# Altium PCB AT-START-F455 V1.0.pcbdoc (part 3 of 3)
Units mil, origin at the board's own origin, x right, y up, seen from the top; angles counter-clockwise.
Board outline 10945.53 x 3554 mil, 2 copper layers (Top Layer, Bottom Layer); 149 components, 197 nets, 740 pads, 768 vias.
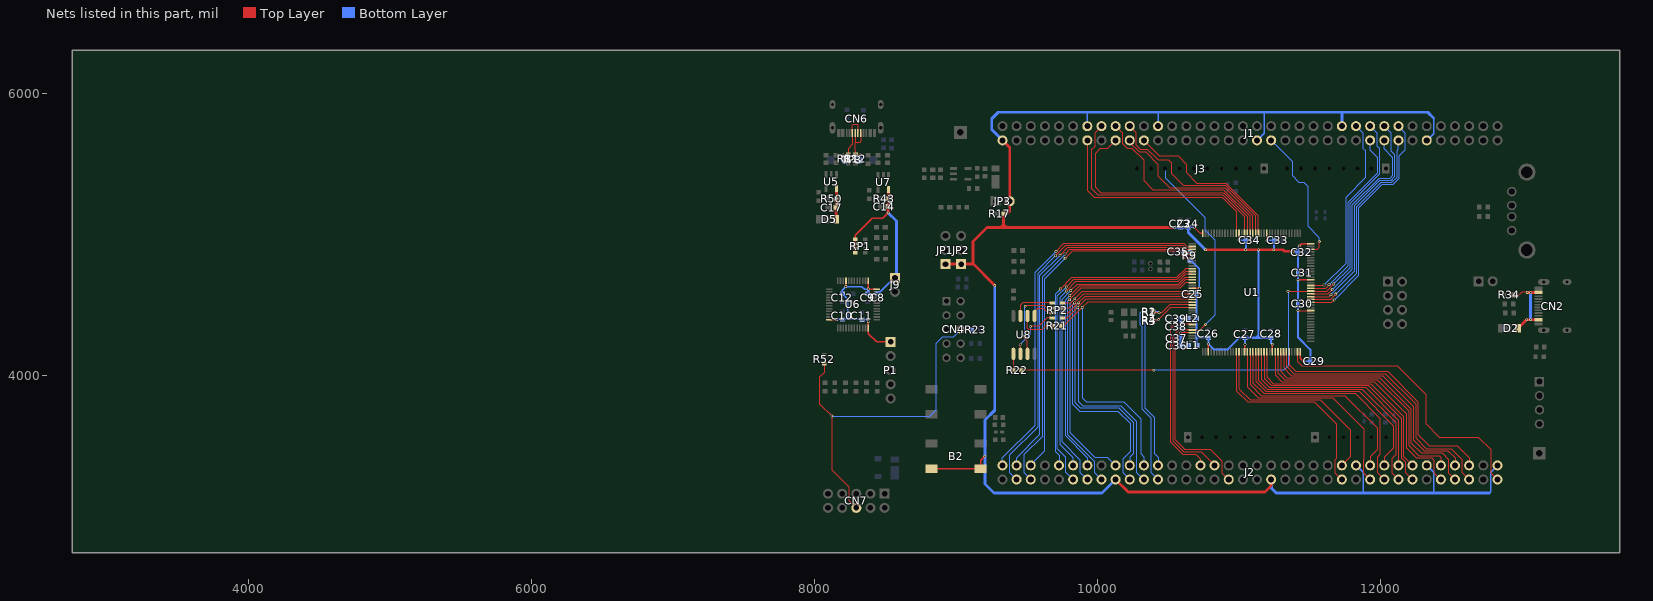
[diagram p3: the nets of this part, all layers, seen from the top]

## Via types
v1: diameter 19.7, hole 11.8, Top Layer to Bottom Layer, 425 vias
v2: diameter 19.68, hole 11.81, Top Layer to Bottom Layer, 331 vias
v3: diameter 31.5, hole 19.68, Top Layer to Bottom Layer, 10 vias
v4: diameter 27.56, hole 19.68, Top Layer to Bottom Layer, 2 vias

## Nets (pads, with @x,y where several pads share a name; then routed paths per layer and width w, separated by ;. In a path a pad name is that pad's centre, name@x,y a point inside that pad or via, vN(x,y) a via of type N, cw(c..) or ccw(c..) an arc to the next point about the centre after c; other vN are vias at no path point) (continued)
PE3: J2.2 U1.2 | length 2667
  Top Layer w6: v2(9708.16,4881.98) 9762.56,4936.38 10610.76,4936.38 10632.36,4914.78 U1.2@10671.86,4914.79
  Bottom Layer w6: J2.2@9329.16,3367.18 9329.16,3419.48 9560.26,3650.58 9560.26,4734.08 v2(9708.16,4881.98)
PE4: J2.3 U1.3 | length 2747.9
  Top Layer w6: v2(9703.83,4849.3) 9777.11,4922.58 10603.26,4922.58 10630.76,4895.08 U1.3@10671.86,4895.11
  Bottom Layer w6: J2.3@9429.17,3267.08 9378.26,3318.08 9378.26,3437.48 9578.26,3637.48 9578.26,4723.73 v2(9703.83,4849.3)
PE5: J2.4 U1.4 | length 2586.6
  Top Layer w6: v2(9736.21,4853.97) 9791.36,4909.18 10595.36,4909.18 10629.16,4875.38 U1.4@10671.86,4875.42
  Bottom Layer w6: J2.4@9429.17,3367.08 9429.16,3421.38 9594.26,3586.48 9594.26,4711.98 v2(9736.21,4853.97)
PE6: J2.5 U1.5 | length 2664.6
  Top Layer w6: v2(9771.79,4861.65) 9805.52,4895.38 10585.96,4895.38 10625.66,4855.68 U1.5@10671.86,4855.74
  Bottom Layer w6: J2.5@9529.16,3267.18 9481.96,3314.38 9481.96,3444.28 9612.26,3574.58 9612.26,4702.12 v2(9771.79,4861.65)
PE7: J2.58 U1.58 | length 1605.7
  Top Layer w6: U1.58@11159.16,4171.68 11159.16,3975.88 11216.06,3918.98 11897.66,3918.98 12129.16,3687.48 J2.58@12129.17,3367.08
PE8: J2.59 U1.59 | length 1740.3
  Top Layer w6: U1.59@11178.76,4171.68 11178.76,3984.18 11229.96,3932.98 11913.96,3932.98 12147.96,3698.98 12147.96,3422.08 12178.26,3391.68 12178.26,3318.08 J2.59@12229.17,3267.08
PE9: J2.60 U1.60 | length 1635.5
  Top Layer w6: U1.60@11198.46,4171.68 11198.46,3992.68 11245.36,3945.78 11935.06,3945.78 12164.76,3716.08 12164.76,3431.48 J2.60@12229.17,3367.08
PE10: J2.63 U1.63 | length 1835.9
  Top Layer w6: U1.63@11257.56,4171.68 11257.56,4006.68 11304.26,3959.98 11956.66,3959.98 12183.66,3733.08 12183.66,3490.58 12254.26,3419.98 12363.16,3419.98 12380.26,3402.88 12380.26,3316.08 J2.63@12429.17,3267.08
PE11: J2.64 U1.64 | length 1749.5
  Top Layer w6: U1.64@11277.26,4171.68 11277.26,4020.88 11323.96,3974.18 11978.36,3974.18 12200.56,3751.98 12200.56,3508.18 12272.76,3435.98 12416.86,3435.98 12429.16,3423.68 J2.64@12429.17,3367.08
PE12: J2.65 U1.65 | length 1887.8
  Top Layer w6: U1.65@11296.86,4171.68 11296.86,4031.28 11339.76,3988.38 11998.46,3988.38 12217.86,3768.98 12217.86,3525.98 12288.86,3454.98 12437.26,3454.98 12480.26,3411.98 12480.26,3316.08 J2.65@12529.17,3267.08
PE13: J2.66 U1.66 | length 1784.8
  Top Layer w6: U1.66@11316.56,4171.68 11316.56,4056.58 11370.56,4002.58 12017.36,4002.58 12233.26,3786.68 12233.26,3546.78 12310.06,3469.98 12479.06,3469.98 12529.16,3419.88 J2.66@12529.17,3367.08
PE14: J2.67 U1.67 | length 1920.6
  Top Layer w6: U1.67@11336.26,4171.68 11336.26,4069.88 11389.36,4016.78 12035.46,4016.78 12250.66,3801.58 12250.66,3562.78 12327.46,3485.98 12501.66,3485.98 12578.26,3409.38 12578.26,3318.08 J2.67@12629.17,3267.08
PE15: J2.68 U1.68 | length 1827.5
  Top Layer w6: U1.68@11355.96,4171.68 11355.96,4079.18 11404.26,4030.98 12053.96,4030.98 12266.36,3818.58 12266.36,3588.48 12347.96,3506.88 12544.16,3506.88 12629.16,3421.88 J2.68@12629.17,3367.08
PF0: J2.10 U1.10 | length 2266
  Top Layer w6: v2@9738.26,4613.98 9817.16,4692.88 10559.16,4692.88 10623.56,4757.28 U1.10@10671.86,4757.31
  Bottom Layer w6: J2.10@9729.26,3367.08 9729.26,3438.98 9702.26,3465.88 9702.26,4577.98 v2@9738.26,4613.98
  other v2: 9738.21,4613.97
PF1: J2.11 U1.11 | length 2370.2
  Top Layer w6: v2(9780.26,4627.98) 9830.56,4678.28 10562.56,4678.28 10621.86,4737.58 U1.11@10671.86,4737.63
  Bottom Layer w6: v2(9780.26,4627.98) 9717.36,4565.08 9717.36,3484.78 9778.26,3423.88 9778.26,3318.08 J2.11@9829.16,3267.18
PF2: J2.12 U1.12 | length 2230
  Top Layer w6: v2(9780.26,4599.98) 9844.36,4664.08 10568.36,4664.08 10622.16,4717.88 U1.12@10671.86,4717.94
  Bottom Layer w6: v2(9780.26,4599.98) 9736.26,4555.98 9736.26,3513.48 9829.16,3420.48 J2.12@9829.17,3367.08
PF3: J2.13 U1.13 | length 2334.4
  Top Layer w6: v2(9812.26,4603.98) 9856.96,4648.68 10571.76,4648.68 10621.36,4698.28 U1.13@10671.86,4698.26
  Bottom Layer w6: v2(9812.26,4603.98) 9751.26,4542.98 9751.26,3533.58 9880.26,3404.48 9880.26,3316.18 J2.13@9929.16,3267.18
PF4: J2.14 U1.14 | length 2192.5
  Top Layer w6: v2@9804.26,4567.98 9870.46,4634.18 10576.36,4634.18 10620.76,4678.58 U1.14@10671.86,4678.57
  Bottom Layer w6: v2@9804.26,4567.98 9772.26,4535.98 9772.26,3578.68 9929.16,3421.78 J2.14@9929.16,3367.18
  other v2: 9804.21,4567.97
PF5: J2.15 U1.15 | length 2295.9
  Top Layer w6: v2(9802.21,4537.97) 9884.16,4619.98 10582.26,4619.98 10621.16,4658.88 U1.15@10671.86,4658.89
  Bottom Layer w6: v2(9802.21,4537.97) 9788.26,4523.18 9788.26,3587.98 9978.26,3397.88 9978.26,3318.08 J2.15@10029.17,3267.08
PF6: J2.18 RP2.4 U1.18 | length 2334.4
  Top Layer w6: RP2.4@9753.18,4516.15 9810.38,4516.15 v2(9840.21,4545.97) 9894.02,4599.78 U1.18@10671.86,4599.83
  Bottom Layer w6: v2(9840.21,4545.97) 9804.26,4509.98 9804.26,3601.88 9980.26,3425.88 10070.36,3425.88 J2.18@10129.16,3367.18
PF7: J2.19 RP2.3 U1.19 | length 2587.3
  Top Layer w6: RP2.3@9753.77,4480.48 cw(c9753.77,4481.3) RP2.3@9753.18,4480.72 9802.95,4480.72 v2(9838.21,4515.97) cw(c9838.28,4515.97) v2(9838.21,4515.97) 9861,4538.79 9902.37,4580.16 U1.19@10671.86,4580.18 ; 9960.77,4580.16 cw(c9960.77,4580.09) 9960.82,4580.14
  Bottom Layer w6: v2@9838.26,4515.98 9822.26,4499.98 9822.26,3803.88 9874.56,3751.58 10145.06,3751.58 10231.76,3664.88 10231.76,3464.78 10178.26,3411.28 10178.26,3318.08 J2.19@10229.16,3267.18
PF8: J2.20 RP2.2 U1.20 | length 2467.4
  Top Layer w6: RP2.2@9754.46,4445.81 ccw(c9754.46,4444.01) RP2.2@9753.18,4445.28 9795.51,4445.28 v2(9866.21,4515.97) 9910.7,4560.46 U1.20@10671.86,4560.46
  Bottom Layer w6: v2(9866.21,4515.97) 9840.26,4489.98 9840.26,3813.88 9880.26,3773.98 10150.66,3773.98 10253.86,3670.78 10253.86,3449.38 10229.16,3424.68 J2.20@10229.17,3367.08
PF9: J2.21 RP2.1 U1.21 | length 2542.3
  Top Layer w6: RP2.1@9753.89,4409.56 cw(c9753.89,4410.55) RP2.1@9753.18,4409.85 9788.08,4409.85 v2(9862.21,4483.97) 9919.02,4540.78 U1.21@10671.86,4540.78
  Bottom Layer w6: v2(9862.21,4483.97) 9864.26,4481.88 9864.26,3820.78 9896.06,3788.98 10166.36,3788.98 10276.26,3679.08 10276.26,3320.08 J2.21@10329.17,3267.08
PF10: J2.22 R21.1 U1.22 | length 2450
  Top Layer w6: R21.1@9744.84,4353.85 9763.43,4353.85 v2(9893.22,4483.63) 9930.67,4521.08 U1.22@10671.86,4521.09 ; v2@9899.22,4483.63 cw(c9900.17,4483.63) v2@9899.5,4484.31
  Bottom Layer w6: v2(9893.22,4483.63) 9893.22,3843.86 9920.1,3816.98 10186.05,3816.98 10307.4,3695.63 10307.4,3451.35 10329.18,3429.57 J2.22@10329.17,3367.08
PF11: J2.49 U1.49 | length 1497.2
  Top Layer w6: U1.49@10981.96,4171.68 10981.96,3896.18 11062.36,3815.78 11534.46,3815.78 11688.26,3661.98 11688.26,3413.98 11680.26,3405.98 11680.26,3316.08 J2.49@11729.17,3267.08
PF12: J2.50 U1.50 | length 1445.9
  Top Layer w6: U1.50@11001.66,4171.68 11001.66,3910.68 11081.96,3830.38 11577.96,3830.38 11788.86,3619.48 11788.86,3426.78 J2.50@11729.17,3367.08
PF13: J2.53 U1.53 | length 1575.8
  Top Layer w6: U1.53@11060.66,4171.68 11060.66,3924.48 11138.96,3846.18 11664.56,3846.18 11884.56,3626.18 11884.56,3409.98 11880.26,3405.68 11880.26,3316.08 J2.53@11929.17,3267.08
PF14: J2.54 U1.54 | length 1544.8
  Top Layer w6: U1.54@11080.36,4171.68 11080.36,3940.78 11160.06,3861.08 11751.16,3861.08 11980.26,3631.98 11980.26,3478.88 11929.16,3427.78 J2.54@11929.17,3367.08
PF15: J2.55 U1.55 | length 1683.1
  Top Layer w6: U1.55@11100.06,4171.68 11100.06,3951.08 11175.46,3875.68 11822.06,3875.68 11996.26,3701.48 11996.26,3442.88 11978.26,3424.88 11978.26,3318.08 J2.55@12029.17,3267.08
PG0: J2.56 U1.56 | length 1620.4
  Top Layer w6: U1.56@11119.76,4171.68 11119.76,3960.88 11190.36,3890.28 11850.66,3890.28 12092.26,3648.68 12092.26,3488.38 12029.16,3425.28 J2.56@12029.17,3367.08
PG1: J2.57 U1.57 | length 1733
  Top Layer w6: U1.57@11139.46,4171.68 11139.46,3967.48 11202.06,3904.98 11874.96,3904.98 12109.56,3670.38 12109.56,3443.88 12080.26,3414.58 12080.26,3316.08 J2.57@12129.17,3267.08
PG2: J1.15 U1.87 | length 1675.9
  Top Layer w6: U1.87@11508.56,4521.08 11659.26,4521.08 v2@11674.26,4535.98
  Bottom Layer w6: v2@11674.26,4535.98 11848.26,4709.98 11848.26,5187.98 12014.26,5353.98 12091.46,5353.98 12136.26,5398.78 12136.26,5557.98 12178.26,5599.98 12178.26,5716.58 J1.15@12129.16,5765.68
  other v2: 11674.21,4535.97
PG3: J1.16 U1.88 | length 1509.4
  Top Layer w6: U1.88@11508.56,4540.78 11648.96,4540.78 v2(11686.21,4577.97)
  Bottom Layer w6: v2(11686.21,4577.97) 11834.26,4725.98 11834.26,5195.98 12006.26,5367.98 12083.36,5367.98 12120.26,5404.88 12120.26,5592.08 12129.16,5600.98 J1.16@12129.16,5665.68
PG4: J1.17 U1.89 | length 1605.8
  Top Layer w6: U1.89@11508.56,4560.48 11638.66,4560.48 v2(11652.21,4573.97)
  Bottom Layer w6: v2(11652.21,4573.97) 11820.26,4741.98 11820.26,5205.98 11998.26,5383.98 12077.66,5383.98 12104.26,5410.58 12104.26,5563.98 12078.26,5589.98 12078.26,5716.58 J1.17@12029.16,5765.68
PG5: J1.18 U1.90 | length 1469.5
  Top Layer w6: U1.90@11508.56,4580.08 11630.36,4580.08 v2(11660.21,4609.97)
  Bottom Layer w6: v2(11660.21,4609.97) 11804.26,4753.98 11804.26,5209.98 11992.26,5397.98 12071.16,5397.98 12090.26,5416.98 12090.26,5543.98 12029.16,5604.98 J1.18@12029.16,5665.68
PG6: J1.19 R22.1 U1.91 | length 4051.1
  Top Layer w6: R22.1@9460.96,4039.98 v2@10399.26,4039.98 ; v2(11348.74,4598.68) 11507.47,4598.69 11508.56,4599.78 11622.06,4599.78 v2(11672.21,4649.97)
  Bottom Layer w6: v2@10399.26,4039.98 11318.26,4039.98 11348.69,4070.41 v2(11348.74,4598.68) ; v2(11672.21,4649.97) 11788.26,4765.98 11788.26,5219.98 11996.26,5427.98 11996.26,5605.98 11978.26,5623.98 11978.26,5716.58 J1.19@11929.16,5765.68
  other v2: 10399.21,4039.97
PG7: J1.20 U1.92 | length 1326
  Top Layer w6: U1.92@11508.56,4619.48 11613.76,4619.48 v2@11638.26,4643.98
  Bottom Layer w6: v2@11638.26,4643.98 11773.46,4779.18 11773.46,5227.18 11982.26,5435.98 11982.26,5542.78 11929.16,5595.88 J1.20@11929.16,5665.68
  other v2: 11638.21,4643.97
PG8: J1.21 U1.93 | length 1370
  Top Layer w6: U1.93@11508.56,4639.18 11599.19,4639.18 v2@11602.82,4642.82
  Bottom Layer w6: v2@11602.82,4642.82 11605.09,4642.82 11758.86,4796.58 11758.86,5264.58 11897.16,5402.88 11897.16,5590.78 11880.26,5607.68 11880.26,5714.58 J1.21@11829.16,5765.68
  other v2: 11602.87,4642.81
PG9: J1.52 U1.124 | length 1212.9
  Top Layer w6: J1.52@10329.16,5665.68 10442.86,5551.98 10574.16,5551.98 10632.26,5493.88 10632.26,5435.98 10708.26,5359.98 10911.16,5359.98 11139.46,5131.68 U1.124@11139.46,5008.28 ; J1.52@10329.18,5665.65 J1.52@10346.21,5648.62
PG10: J1.53 U1.125 | length 1371.6
  Top Layer w6: J1.53@10229.16,5765.68 10276.26,5718.58 10276.26,5631.98 10308.26,5599.98 10358.26,5599.98 10434.26,5523.98 10506.16,5523.98 10526.26,5503.98 10526.26,5429.18 10611.36,5343.98 10908.16,5343.98 11119.76,5132.38 U1.125@11119.76,5008.28
PG11: J1.54 U1.126 | length 1274.2
  Top Layer w6: J1.54@10229.16,5665.68 10229.16,5648.98 10298.16,5579.98 10346.26,5579.98 10432.26,5493.98 10432.26,5409.98 10514.26,5327.98 10903.29,5327.98 11099.21,5132.06 11099.26,5009.18 U1.126@11100.06,5008.28
PG12: J1.55 U1.127 | length 1463.6
  Top Layer w6: J1.55@10129.16,5765.68 10178.26,5716.58 10178.26,5641.98 10214.26,5605.98 10248.26,5605.98 10330.26,5523.98 10330.26,5379.98 10396.26,5313.98 10895.26,5313.98 11080.36,5128.78 U1.127@11080.36,5008.28
PG13: J1.56 U1.128 | length 1702.1
  Top Layer w6: J1.56@10129.16,5665.68 10069.46,5605.98 10018.26,5605.98 9984.57,5572.29 9984.57,5335.62 10024.22,5295.97 10893.3,5295.97 11059.21,5130.06 11059.26,5009.78 U1.128@11060.66,5008.28
PG14: J1.57 U1.129 | length 1753.7
  Top Layer w6: J1.57@10029.16,5765.68 9980.26,5716.68 9980.26,5619.98 9957.57,5597.29 9957.57,5326.37 10003.96,5279.98 10888.06,5279.98 11039.86,5128.18 11039.86,5009.38 U1.129@11040.96,5008.31
PG15: J1.60 U1.132 | length 1624.2
  Top Layer w6: J1.60@9929.16,5665.68 9929.16,5312.98 9978.23,5263.98 10882.26,5263.98 10983.21,5163.03 10983.26,5009.48 U1.132@10981.96,5008.28
PH0/HEXT_IN: R1.2 R2.2 U1.23 | length 357.4
  Top Layer w6: R1.2@10387.76,4447.98 10389.56,4446.18 v2(10435.86,4446.18) 10455.13,4446.18 10510.33,4501.38 U1.23@10671.86,4501.41
  Bottom Layer w6: R2.2@10388.85,4452.62 10429.42,4452.62 v2(10435.86,4446.18)
PH0_E: J2.23 R2.1 | length 1278.9
  Bottom Layer w6: R2.1@10344.45,4452.62 10309.57,4452.62 10298.76,4441.8 10298.76,4365.43 10314.46,4349.73 10314.46,3767.38 10379.46,3702.28 10379.46,3316.78 J2.23@10429.17,3267.08
PH1/HEXT_OUT: R3.2 R4.2 U1.24 | length 365.2
  Top Layer w6: R3.2@10387.76,4393.98 10428.26,4393.98 v2(10432.26,4397.98) 10515.96,4481.68 U1.24@10671.86,4481.72
  Bottom Layer w6: R4.2@10388.85,4394.62 10428.9,4394.62 v2(10432.26,4397.98)
PH1_E: J2.24 R4.1 | length 1063.9
  Bottom Layer w6: R4.1@10335.06,4391.98 10335.06,3775.08 10401.16,3708.98 10401.16,3453.88 10429.16,3425.88 J2.24@10429.17,3367.08
PH2: J1.34 U1.106 | length 986.1
  Top Layer w6: U1.106@11508.56,4895.08 11555.36,4895.08 11570.16,4909.88 v2@11570.16,4949.38
  Bottom Layer w6: J1.34@11229.16,5665.68 11230.56,5665.68 11381.86,5514.38 11381.86,5413.88 11428.36,5367.38 11463.36,5367.38 11491.76,5338.98 11491.76,5056.43 11570.16,4978.03 v2@11570.16,4949.38
  other v2: 11570.17,4949.34
PH3: J2.71 U1.71 | length 2046.3
  Top Layer w6: U1.71@11415.06,4171.68 11415.06,4101.68 11446.53,4070.32 12121.41,4070.32 12322.57,3869.17 12322.57,3663.37 12418.36,3567.58 12692.66,3567.58 12780.26,3479.88 12780.26,3316.08 J2.71@12829.17,3267.08
PH4: J2.30 U1.30 | length 1275.9
  Top Layer w6: U1.30@10671.86,4363.61 10548.56,4363.61 10515.57,4330.61 10515.57,3534.61 10603.57,3446.61 10695.57,3446.61 10729.17,3413.01 J2.30@10729.17,3367.08
QSPI1_CS: R22.2 U8.1 | length 116
  Top Layer w6: R22.2@9405.96,4039.98 9406.16,4040.18 U8.1@9406.16,4155.92
QSPI1_IO0: RP2.7 U8.5 | length 176.4
  Top Layer w6: U8.5@9556.16,4423.64 9556.16,4453.17 9579.6,4476.61 9617.57,4476.61 9648.91,4445.28 RP2.7@9680.35,4445.28
QSPI1_IO1: RP2.8 U8.2 | length 401.8
  Top Layer w5.98: U8.2@9456.16,4155.92 v2(9456.18,4222.41)
  Top Layer w6: v2(9526.59,4349.49) 9586.44,4349.49 9646.8,4409.85 RP2.8@9680.35,4409.85 ccw(c9680.11,4409.6) RP2.8@9680.11,4409.95
  Bottom Layer w6: v2(9456.18,4222.41) 9456.18,4223.22 9526.59,4293.63 v2(9526.59,4349.49)
QSPI1_IO2: RP2.6 U8.3 | length 552.2
  Top Layer w5.98: v2(9482.61,4281.14) 9482.61,4267.58 9506.16,4244.03 U8.3@9506.16,4155.92
  Top Layer w6: v2(9489.97,4492.3) 9498.29,4500.61 9625.57,4500.61 9645.47,4480.72 RP2.6@9680.35,4480.72
  Bottom Layer w5.98: v2(9482.61,4281.14) 9481.57,4282.18 9481.57,4483.9 v2(9489.97,4492.3)
QSPI1_IO3: RP2.5 U8.7 | length 307.3
  Top Layer w6: U8.7@9455.57,4424.23 ccw(c9456.18,4424.23) U8.7@9456.16,4423.64 ; U8.7@9455.56,4424.28 9455.56,4498.6 9473.1,4516.15 RP2.5@9680.35,4516.15
QSPI1_SCK: R21.2 U8.6 | length 287.1
  Top Layer w6: U8.6@9506.16,4423.64 9506.16,4374.87 9499.57,4368.29 9499.57,4340.61 9511.57,4328.61 9609.57,4328.61 9634.8,4353.85 R21.2@9685.52,4353.85
SWO: CN4.6 CN7.6 R23.1 R52.2 | length 2661.3
  Top Layer w6: 8070.23,4023.63 8035.17,3988.57 8035.17,3804.01 v2(8122.8,3716.38) 8124.77,3714.41 8124.77,3332.21 8245.21,3211.77 8245.21,3116.85 CN7.6@8295.43,3066.63 ; 8070.26,4023.68 R52.2@8070.26,4081.58
  Bottom Layer w6: v2(8122.8,3716.38) 8124.56,3714.61 8815.89,3714.61 8860.26,3758.98 8860.26,4231.98 8906.26,4277.98 8984.36,4277.98 9034.56,4328.18 9112.76,4328.18 R23.1@9112.76,4325.98
USBM: CN6.A7 CN6.B7 R12.1 TP3.2 | length 334.9
  Top Layer w6: CN6.A7@8287.41,5717.9 8287.41,5649.64 ; v2(8324.77,5565.01) 8324.24,5564.48 R12.1@8290.08,5564.48 8290.08,5586.36 8287.41,5589.03 8287.41,5649.64 ; CN6.B7@8326.71,5717.9 8326.71,5657.74 8318.61,5649.64 8287.41,5649.64
  Bottom Layer w6: TP3.2@8314.58,5526.61 8324.77,5536.8 v2(8324.77,5565.01)
USBP: CN6.A6 CN6.B6 R11.1 TP3.3 | length 398.8
  Top Layer w6: v2(8203.57,5563.81) 8203.69,5563.69 R11.1@8238.07,5563.69 8238.07,5607.32 8267.71,5636.95 CN6.B6@8267.71,5717.9 8267.71,5774.07 8272.74,5779.1 8302.29,5779.1 8307.01,5774.39 CN6.A6@8307.01,5717.9
  Bottom Layer w6: v2(8203.57,5563.81) 8203.57,5537.62 TP3.3@8214.58,5526.61
VBAT: C35.1 J2.6 R9.1 U1.6 | length 2722.4
  Top Layer w6: v2(9772.21,4831.97) 9821.36,4881.18 10566.96,4881.18 v2(10611.21,4836.97) 10612.06,4836.08 U1.6@10671.86,4836.08
  Top Layer w10: v2(10611.21,4836.97) U1.6@10671.86,4836.08
  Bottom Layer w6: J2.6@9529.17,3367.08 9529.16,3370.98 9628.26,3470.08 9628.26,4687.98 v2(9772.21,4831.97) ; C35.1@10598.77,4875.97 10654.76,4875.98 R9.1@10655.26,4875.48
  Bottom Layer w10: v2(10611.21,4836.97) 10611.16,4863.48 10598.66,4875.98 R9.1@10655.16,4875.48
VBUS: CN2.A4B9 CN2.B4A9 D2.2 R34.2 | length 552.1
  Top Layer w5.98: 12981.88,4572.61 12999.58,4590.32 v1(13039.74,4590.32)
  Top Layer w6: R34.2@12941.23,4572.61 12981.88,4572.61
  Top Layer w20: D2.2@12974.39,4335.82 v1(13035.89,4397.32) v1(13063.79,4397.32) CN2.A4B9@13120.94,4397.32 ; v1(13039.74,4590.32) CN2.B4A9@13120.94,4590.32
  Bottom Layer w20: v1(13063.79,4397.32) v1(13063.79,4589.97) v1@13064.04,4590.22
VCC: C8.2 C9.2 C10.2 C11.2 C12.2 C14.2 J9.1 P1.1 R43.1 RP1.1 RP1.2 RP1.3 RP1.4 U6.1 U6.9 U6.24 U6.36 U6.48 U7.5 | length 2489.8
  Top Layer w10: U6.24@8104.56,4397.08 8154.68,4397.08 v2(8155.18,4396.59) ; v2(8221.57,4631.81) 8222.69,4632.94 U6.9@8222.69,4672.63 ; RP1.4@8289.33,4870.97 RP1.3@8289.33,4902.46 RP1.2@8289.33,4933.96 RP1.1@8289.33,4965.45 8289.33,4994.38 8409.97,5115.01 8482.37,5115.01 v2(8520.77,5153.41) ; v2(8379.97,4385.01) 8380.17,4384.81 U6.36@8380.17,4337.98 8380.16,4298.64 8438.61,4240.18 P1.1@8538.16,4240.18 ; U6.1@8380.16,4672.68 8380.16,4632.38 8380.46,4632.08 v2(8380.46,4613.78) 8400.16,4613.78 8400.36,4613.58 U6.48@8439.26,4613.58
  Top Layer w20: v2(8520.77,5153.41) 8519.37,5154.82 C14.2@8519.37,5197.16 8524.34,5202.13 U7.5@8524.34,5318.39
  Bottom Layer w6: C10.2@8196.77,4398.65 C10.2@8198.74,4398.65
  Bottom Layer w10: v2(8155.18,4396.59) 8170.98,4396.59 8173.05,4398.65 C10.2@8196.77,4398.65 ; C10.2@8198.74,4398.65 8235.87,4398.65 ; v2(8379.97,4385.01) 8369.13,4395.85 C11.2@8335.17,4395.85 8332.01,4399.01 8299.97,4399.01 8299.61,4398.65 8235.87,4398.65 ; v2(8380.46,4613.78) 8353.6,4613.78 8335.57,4631.81 v2(8221.57,4631.81) 8196.37,4606.61 C12.2@8196.37,4579.77 8198.34,4579.77 8235.57,4542.54 8235.57,4398.95 8235.87,4398.65
  Bottom Layer w15: v2(8380.46,4613.78) 8380.46,4584.26 C9.2@8376.37,4580.17 8445.57,4580.17 C8.2@8446.37,4580.97 8450.73,4580.97 8563.33,4693.58 J9.1@8569.46,4693.58
  Bottom Layer w20: v2(8520.77,5153.41) 8579.57,5094.61 8579.57,4703.69 J9.1@8569.46,4693.58
VCC3.5V: C17.2 D5.2 R50.1 U5.5 | length 217
  Top Layer w20: D5.2@8152.36,5107.05 U5.5@8155.56,5324.05
VDD: B2.1 B2.3 C23.1 C24.1 C25.1 C26.1 C27.1 C28.1 C29.1 C30.1 C31.1 C32.1 C33.1 C34.1 J1.12 J1.23 J1.36 J1.49 J1.59 J1.72 J2.17 J2.39 J2.52 J2.62 J2.72 JP1.1 JP2.1 JP3.2 L1.1 L2.1 R9.2 R17.2 U1.17 U1.39 U1.52 U1.62 U1.72 U1.84 U1.95 U1.108 U1.121 U1.131 U1.144 | length 18180.8
  Top Layer w6: v2@10686.26,5049.98 10727.86,5008.28 ; v2(11001.21,4959.97) 11001.16,5007.88 U1.131@11001.66,5008.28 ; v2@11198.26,4955.98 11198.26,5007.98 U1.121@11198.46,5008.28 ; v2(11237.21,4223.97) 11237.86,4223.28 U1.62@11237.86,4171.68 ; v2(11419.26,4462.98) 11420.26,4461.98 11508.36,4461.98 U1.84@11508.56,4461.98
  Top Layer w10: B2.3@8828.03,3344.39 B2.1@9174.49,3344.39 9174.46,3402.18 v2@9204.26,3431.98 ; U1.17@10671.86,4619.52 v2(10722.29,4619.56) ; 10727.86,5008.28 U1.144@10745.68,5008.31 ; U1.39@10785.06,4171.68 v2(10785.09,4224.97) ; v2(11001.21,4959.97) U1.131@11001.66,5008.28 ; U1.52@11040.96,4171.68 11040.96,4218.78 v2@11044.26,4221.98 ; v2@11198.26,4955.98 U1.121@11198.46,5008.28 ; v2(11237.21,4223.97) U1.62@11237.86,4171.68 ; v2(11419.26,4678.58) U1.95@11508.48,4678.57 ; v2(11428.26,4917.98) 11444.76,4934.48 U1.108@11508.48,4934.48 ; U1.72@11434.66,4171.68 11434.66,4125.48 v2@11459.26,4100.98 ; U1.84@11508.36,4461.98 U1.84@11508.46,4462.08
  Top Layer w20: JP1.1@8926.26,4789.98 9036.26,4789.98 9121.56,4789.98 ; v2(9275.08,4638.41) 9123.56,4789.98 9121.56,4789.98 ; J1.72@9329.18,5665.65 9380.21,5614.62 JP3.2@9380.21,5234.97 ; JP3.2@9380.21,5234.97 9380.16,5164.98 9362.26,5146.98 9335.76,5146.98 9335.86,5070.28 ; J2.17@10129.17,3267.08 10218.28,3177.97 11185.21,3177.97 11229.18,3221.93 J2.39@11229.17,3267.08 ; v2@10543.26,5048.98 9357.26,5048.98 ; v2(10765.65,4891.76) 10765.87,4891.98 v2@11048.26,4891.98 ; v2(11048.21,4891.97) v2(11247.21,4891.97) 11312.67,4891.97 11323.77,4880.87 v1(11387.81,4880.87) ; 9121.56,4789.98 9121.56,4951.28 9219.26,5048.98 9315.36,5048.98 ; 9315.36,5048.98 9335.86,5070.28 ; 9315.36,5048.98 9357.26,5048.98 ; 9335.86,5070.28 9357.26,5048.98
  Bottom Layer w6: v2(11001.21,4959.97) v2@11002.16,4958.98 ; C32.1@11418.02,4872.73 C32.1@11418.02,4879.87 ; v2@11459.26,4100.98 v2@11460.26,4101.98
  Bottom Layer w10: J1.59@9929.18,5765.65 9929.18,5862.18 9931.37,5864.38 ; J1.49@10429.18,5765.65 10432.2,5768.67 10432.2,5864.38 ; C24.1@10643.21,5049.41 10685.65,5049.41 v2(10686.21,5049.97) ; R9.2@10655.16,4820.48 10658.06,4820.48 10722.26,4756.28 v2(10722.29,4619.56) 10700.76,4597.98 ; v2@11001.16,4958.98 11002.16,4958.98 C34.1@11050.76,4958.98 ; J1.36@11129.18,5665.65 11179.27,5715.74 11179.27,5864.38 ; v2@11198.26,4955.98 11200.16,4957.98 C33.1@11249.65,4957.97 ; C32.1@11419.02,4880.87 11419.02,4908.74 v2(11428.26,4917.98) ; C30.1@11420.01,4508.61 11422.36,4510.97 C30.1@11431.65,4510.97 ; v2@11459.26,4100.98 11460.16,4101.98 11460.26,4101.98 C29.1@11506.65,4101.97 ; J2.52@11829.17,3367.08 11879.21,3317.04 11879.21,3170.98 ; J2.62@12329.17,3367.08 12379.21,3317.04 12379.21,3170.98 ; J1.12@12329.18,5665.65 12377.21,5713.68 12377.21,5823.97 ; 12771.26,3170.98 12780.26,3179.98 12780.26,3318.08 J2.72@12829.17,3367.08
  Bottom Layer w15: 10700.76,4597.98 10701.87,4596.87 L2.1@10701.88,4406.61 10701.87,4270.79 10701.56,4270.48 ; L1.1@10705.57,4214.98 10701.56,4218.98 10701.56,4270.48 ; C27.1@11043.26,4268.48 11003.66,4268.48 10922.88,4187.61 10823.59,4187.61 10785.06,4226.01 10785.26,4270.48 10701.56,4270.48 ; C27.1@11043.26,4269.48 11122.36,4269.48 ; v2@11044.26,4221.98 C27.1@11044.26,4267.48 ; v2@11048.26,4891.98 11050.76,4891.98 C34.1@11050.76,4958.98 ; 11138.66,4285.98 11122.36,4269.48 ; v2(11138.7,4890.97) 11138.7,4285.98 11155.2,4269.48 ; v2@11237.26,4223.98 11228.26,4232.98 11228.26,4269.48 11155.2,4269.48 ; v2(11247.21,4891.97) 11249.66,4894.48 C33.1@11249.65,4957.97 ; v2@11418.01,4454.73 11418.01,4273.17 11420.01,4271.17 11506.65,4184.53 C29.1@11506.65,4101.97 ; v2@11420.01,4462.77 C30.1@11420.01,4508.61 C32.1@11420.01,4872.61 ; 11122.36,4269.48 11155.2,4269.48
  Bottom Layer w20: v2(9275.08,4638.41) 9275.08,3756.83 9205.26,3687.01 9205.26,3235.98 9270.26,3170.98 10033.06,3170.98 J2.17@10129.17,3267.08 ; J1.72@9329.16,5665.68 9253.46,5741.38 9253.46,5818.28 9299.56,5864.38 9931.37,5864.38 10432.2,5864.38 11179.27,5864.38 11729.18,5864.38 ; v2(10543.21,5048.97) 10587.57,5048.97 10642.77,5048.97 C24.1@10643.21,5049.41 10643.21,5014.2 v2(10765.65,4891.76) ; J2.39@11229.17,3267.08 11231.21,3265.04 11231.21,3204.97 11265.2,3170.98 11879.21,3170.98 12379.21,3170.98 12771.26,3170.98 ; v1(11387.81,4880.87) C32.1@11418.01,4880.87 ; J1.23@11729.18,5765.65 11729.18,5864.38 ; 12377.26,5823.98 12336.76,5864.38 11729.18,5864.38
  other v2: 9204.21,3431.97 11459.21,4100.97 11044.21,4221.97 11198.21,4955.97
VDDA: C36.1 C37.1 J2.33 L1.2 U1.33 | length 1590.7
  Top Layer w6: U1.33@10671.86,4304.56 10588.86,4304.58 10548.16,4263.88 10548.16,3552.03 10619.2,3480.98 10799.46,3480.98 10880.26,3400.18 10880.26,3316.08 J2.33@10929.17,3267.08
  Bottom Layer w6: v2@10588.26,4303.98 10588.66,4303.48 C37.1@10588.66,4264.98 ; L1.2@10642.86,4212.98 L1.2@10644.94,4214.98
  Bottom Layer w20: v2@10588.26,4303.98 10588.66,4264.98 10588.66,4212.98 L1.2@10642.86,4212.98 ; L1.2@10642.96,4212.98 L1.2@10644.96,4214.98
  other v2: 10588.21,4303.97
VREF+: C38.1 C39.1 J2.32 J3.8 L2.2 U1.32 | length 2915.4
  Top Layer w6: v2(10616.21,4324.97) 10671.16,4324.98 U1.32@10671.86,4324.24 ; v2@10765.66,4363.98 10725.86,4324.18 U1.32@10671.86,4324.24 ; J2.32@10829.17,3367.08 10734.26,3461.98 10612.2,3461.98 10531.56,3542.63 10531.56,4281.28 10574.46,4324.18 U1.32@10671.86,4324.24
  Bottom Layer w6: J3.8@10479.86,5465.98 10479.86,5400.33 10758.26,5121.93 10758.26,5033.65 10828.93,4962.97 10828.93,4427.25 v2@10765.66,4363.98 ; C39.1@10586.77,4404.97 10586.76,4348.98 C38.1@10587.13,4348.61 ; L2.2@10639.53,4404.98 L2.2@10641.25,4406.61
  Bottom Layer w20: v2(10616.21,4324.97) 10610.76,4324.98 C38.1@10587.13,4348.61 10587.12,4404.62 C39.1@10586.77,4404.97 L2.2@10639.53,4404.98 ; L2.2@10639.63,4404.98 L2.2@10641.27,4406.61
  other v2: 10765.63,4364
pads on no net: CN2.A8 CN2.B8 CN6.A8 CN6.B8 J4.1 J4.8 U6.2 U6.3 U6.4 U6.5 U6.6 U6.14 U6.15 U6.16 U6.17 U6.18 U6.21 U6.22 U6.29 U6.38 U6.41 U6.42 U6.43 U6.45 U6.46
copper on no net:
  other v2: 13244.53,4083.29 12457.13,4988.8 12260.28,5067.54 12398.07,5067.54

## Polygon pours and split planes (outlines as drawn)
GND on Top Layer (solid, remove dead copper, pour order 0): 7929.57,6050.61 13442.97,6050.61 13442.97,3000.61 7929.57,3000.61
GND on Bottom Layer (solid, remove dead copper, pour order 2): 7904.5,6054 13445.53,6054 13445.53,3000 7904.5,3000

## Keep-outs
Top Layer:
  region: 8093.57,6044.61 8503.57,6044.61 8503.57,5692.61 8093.57,5692.61
  region: 11000.57,5092.61 11028.57,5092.61 11028.57,5089.61 11000.57,5089.61
  region: 8427.33,4456.25 8427.33,4435.51 8454.37,4435.51 8454.37,4456.25 8427.4,4456.25
  region: 9705.37,4533.67 9727.83,4533.67 9727.83,4528.15 9705.37,4528.15
Board Outline Layer:
  circle w1: c12139.81,4865.97 r62.99
  circle w10: c12139.81,4865.97 r62.99
  circle w1: c10139.81,5465.96 r62.99
  circle w10: c10139.81,5465.96 r62.99
  circle w1: c10089.81,3565.97 r62.99
  circle w10: c10089.81,3565.97 r62.99
  circle w1: c8818.39,5874.63 r62.99
  circle w10: c8818.39,5874.63 r62.99
  circle w1: c8818.39,3158.09 r62.99
  circle w10: c8818.39,3158.09 r62.99
  circle w1: c13109.73,3158.09 r62.99
  circle w10: c13109.73,3158.09 r62.99
  circle w1: c13109.73,5874.63 r62.99
  circle w10: c13109.73,5874.63 r62.99
  lines w8: 8582.96,6032.21 cw(c8582.96,5953.47) 8661.7,5953.47 8661.7,5631.63 8701.21,5631.63 8701.21,5953.46 cw(c8779.95,5953.46) 8779.95,6032.2 ; 8583.39,3000.61 ccw(c8583.39,3079.35) 8662.13,3079.35 8662.16,3079.38 8662.16,3518.58 8700.96,3518.58 8700.96,3079.38 8700.96,3079.35 ccw(c8779.7,3079.35) 8779.7,3000.61 ; 8661.66,5546.58 8661.66,5553.58 8701.26,5553.58 8701.26,5546.58 8701.22,5546.58 8701.22,5224.75 8701.22,4903.97 ; 8661.7,5546.59 8661.7,5224.75 8661.7,4904.49 ; 8661.7,4904.49 8662.57,4903.61 ; 8661.7,4904.49 ccw(c8662.57,4904.49) 8662.57,4903.61 ; 8662.57,4903.61 8700.86,4903.61 ; 8700.86,4903.61 8701.22,4903.97 ; 8700.86,4903.61 ccw(c8700.86,4903.97) 8701.22,4903.97 ; 8661.57,3606.61 8661.57,3698.61 8701.57,3698.61 8701.57,3606.61 8661.57,3606.61 ; 8661.57,3810.61 8661.57,4809.61 8661.57,4825.61 8680.57,4825.61 8700.57,4825.61 8700.57,3825.61 8700.57,3810.61 8699.57,3810.61 8661.57,3810.61
  lines w10: 7929.57,3079.35 ccw(c8008.31,3079.35) 8008.31,3000.61 13362.64,3000.61 ccw(c13362.64,3079.35) 13441.38,3079.35 13441.38,5953.37 ccw(c13362.64,5953.37) 13362.64,6032.11 8008.31,6032.11 ccw(c8008.31,5953.37) 7929.57,5953.37 7929.57,3079.35

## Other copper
Top Layer:
  drawing of 864 lines, arcs and shapes, not listed
Bottom Layer:
  drawing of 533 lines, arcs and shapes, not listed

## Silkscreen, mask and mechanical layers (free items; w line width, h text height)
Top Silkscreen Layer:
  region: 12061.06,5334.85 12023.06,5334.85 12043.06,5354.85 12063.06,5334.85
  region: 11922.7,5352.85 11960.7,5352.85 11940.7,5332.85 11920.7,5352.85
  lines w6: 8141.98,3304.61 8141.98,3603.61 ; 8238.38,3304.61 8238.38,3603.61 ; 8334.77,3303.61 8334.77,3603.61 ; 8431.17,3309.61 8431.17,3603.61
  lines w8: 8243,3218.63 8243,3258.63 8343,3258.63 8343,3217.63 ; 8533.55,3272.63 8496.55,3235.63 8457.55,3274.63 8533.55,3274.63 ; 8842.11,4558.1 8875.56,4528.18 8841.33,4499.39 8841.33,4557.7 8842.9,4557.31 ; 8881.91,4376.46 8859.05,4376.46 8859.05,4277.18 8882.06,4277.18 8882.06,4278.37
  lines w10: 10652.7,5212.76 12068.4,5212.76 ; 10942.92,3858.17 11395.93,3858.17 ; 11541.16,3858.17 12101.16,3858.17 ; 12759.36,3803.43 13039.36,3803.43 ; 12759.49,3703.74 13039.49,3703.74 ; 12759.48,3903.55 13039.48,3903.55
  text "143" at 9294.03,5925.4 h53.08
  text "133" at 9778.67,5925.4 h53.08
  text "123" at 10283.4,5925.34 h53.08
  text "113" at 10800.72,5925.42 h53.08
  text "103" at 11286.94,5925.43 h53.08
  text "93" at 11797.25,5925.41 h53.08
  text "83" at 12303.16,5925.43 h53.08
  text "73" at 12798.04,5925.41 h53.08
  text "D8" at 12614.84,5826.64 h53.08 r45
  text "B12" at 12814.13,5827.4 h53.08 r45
  text "E0" at 9430.12,5824.52 h53.08 r45
  text "D7" at 10318.9,5825.28 h53.08 r45
  text "D12" at 12415.09,5824.62 h53.08 r45
  text "D10" at 12514.89,5825.31 h53.08 r45
  text "B14" at 12714.99,5825.34 h53.08 r45
  text "B8" at 9526.51,5823.55 h53.08 r45
  text "B3" at 9826.63,5823.87 h53.08 r45
  text "D1" at 10725.32,5823.89 h53.08 r45
  text "A14" at 11016.9,5823.66 h53.08 r45
  text "A13" at 11214.65,5823.89 h53.08 r45
  text "A11*" at 11319.48,5823.92 h53.08 r45
  text "A9" at 11426.06,5823.63 h53.08 r45
  text "D14" at 12219.86,5823.66 h53.08 r45
  text "B5" at 9727.99,5823.17 h53.08 r45
  text "D5" at 10530.89,5822.21 h53.08 r45
  text "D3" at 10626.84,5822.42 h53.08 r45
  text "B7" at 9625.2,5820.13 h53.08 r45
  text "G10" at 10218.23,5820.36 h53.08 r45
  text "G8" at 11820.07,5819.93 h53.08 r45
  text "G12" at 10118.32,5818.91 h53.08 r45
  text "GND" at 11114.44,5819.33 h53.08 r45
  text "G2" at 12119.89,5819.18 h53.08 r45
  text "GND" at 9334.9,5817.96 h53.08 r45
  text "C7" at 11625.79,5817.66 h53.08 r45
  text "G6" at 11922.73,5818.3 h53.08 r45
  text "C12" at 10818.19,5816.54 h53.08 r45
  text "C9" at 11519.64,5817.36 h53.08 r45
  text "G4" at 12017.33,5817.43 h53.08 r45
  text "GND" at 12312.34,5817.24 h53.08 r45
  text "G14" at 10017.34,5816.49 h53.08 r45
  text "VDD" at 10418.16,5815.77 h53.08 r45
  text "C10" at 10920.36,5815.82 h53.08 r45
  text "VDD" at 11710.07,5815.74 h53.08 r45
  text "VDD" at 9913.84,5812.5 h53.08 r45
  text "GND" at 8977.64,5808.6 h61.93
  text "B6" at 9742.77,5537.36 h53.08 r45
  text "B9" at 9540.12,5533.83 h53.08 r45
  text "E1" at 9435.76,5530.95 h53.08 r45
  text "B4" at 9835.99,5531.15 h53.08 r45
  text "D6" at 10432.23,5530.95 h53.08 r45
  text "G11" at 10230.83,5527.56 h53.08 r45
  text "D4" at 10637.55,5524.86 h53.08 r45
  text "G13" at 10109.58,5524.31 h53.08 r30
  text "G9" at 10324.42,5524.4 h53.08 r45
  text "D0" at 10838.83,5524.06 h53.08 r45
  text "G5" at 12031.09,5523.75 h53.08 r45
  text "G3" at 12133.79,5523.58 h53.08 r45
  text "D2" at 10739.23,5522.71 h53.08 r45
  text "H2" at 11232.67,5523.43 h53.08 r45
  text "C6" at 11737.72,5522.99 h53.08 r45
  text "G7" at 11932.92,5522.76 h53.08 r45
  text "A8" at 11533.03,5521.69 h53.08 r45
  text "C8" at 11633,5522.25 h53.08 r45
  text "C11" at 10934.3,5519.65 h53.08 r45
  text "A10" at 11429.72,5519.73 h53.08 r45
  text "G15" at 9928.83,5517.95 h53.08 r45
  text "D11" at 12532.33,5516.61 h53.08 r45
  text "A15" at 11025.3,5515.46 h53.08 r45
  text "D15" at 12226.07,5515 h53.08 r45
  text "D9" at 12634.99,5513.64 h53.08 r45
  text "VDD" at 9317.08,5512.52 h53.08 r45
  text "GND" at 11820.45,5513.47 h53.08 r45
  text "GND" at 10021.29,5511.87 h53.08 r45
  text "GND" at 10526.54,5511.97 h53.08 r45
  text "A12*" at 11322.84,5511.95 h53.08 r45
  text "B15" at 12734.91,5511.09 h53.08 r45
  text "D13" at 12427.78,5509.01 h53.08 r45
  text "B13" at 12832.59,5509.41 h53.08 r45
  text "VDD" at 11121.07,5507.7 h53.08 r45
  text "VDD" at 12323.24,5503.68 h53.08 r45
  text "BOOT0" at 9597.79,5485.43 h44.24 r45
  text "HOST" at 13163.09,5483.02 h80
  text "4" at 11676.82,5362.91 h69.7 r90
  text "8" at 11216.74,5361.97 h69.7 r90
  text "7" at 11379.82,5361.91 h69.7 r90
  text "2" at 11873.82,5361.91 h69.7 r90
  text "13" at 10719.33,5322.2 h70.78 r90
  text "12" at 10819.33,5322.2 h70.78 r90
  text "#6" at 11476.41,5316.14 h70.78 r90
  text "#5" at 11577.41,5316.14 h70.78 r90
  text "#9" at 11120.33,5315.2 h70.78 r90
  text "#3" at 11776.41,5315.14 h70.78 r90
  text "#11" at 10920.62,5295.36 h70.78 r90
  text "#10" at 11019.98,5289.01 h70.78 r90
  text "GND" at 10621.15,5268.8 h70.78 r90
  text "SCL" at 10315.33,5266.66 h70.78 r90
  text "SDA" at 10415.33,5266.66 h70.78 r90
  text "RX 0" at 12081.98,5235.78 h70.78 r90
  text "TX 1" at 11978.75,5234.59 h70.78 r90
  text "DIGITAL(#=PWM)" at 11091.16,5233.28 h61.93
  text "AREF" at 10519.33,5230.13 h70.78 r90
  text "IDD" at 9470.36,5181.95 h88.47
  text "LD:" at 8563.5,5173.13 h72 r270
  text "1" at 8564.8,5059.26 h72 r270
  text "BOOT0" at 8780.66,5046.26 h61.93
  text "BOOT1" at 9002.5,5046.34 h61.93
  text "AT-Link-EZ V1.4" at 7962.83,5043.28 h88.47 r270
  text "2" at 8564.01,4994.65 h72 r270
  text "GND" at 9102.99,4961.2 h61.93
  text "GND" at 8752.93,4958.23 h61.93
  text "3" at 8562.83,4916.24 h72 r270
  text "4" at 8563.62,4842.17 h72 r270
  text "VDD" at 9107.84,4761.9 h53.08
  text "VDD" at 8764.81,4752.09 h53.08
  text "PA9" at 12618.57,4739.61 h61.93
  text "VBUS" at 12761.57,4739.61 h61.93
  text "DEVICE" at 13140.45,4713.3 h82.58
  text "MISO" at 11855.88,4637.16 h61.93
  text "5V" at 12243.86,4635.19 h61.93
  text "MOSI" at 12227.93,4534.8 h61.93
  text "SCK" at 11869.55,4528.11 h61.93
  text "5V" at 9142.77,4499.98 h61.93
  text "3V3" at 8717.21,4492.94 h61.93
  text "NRST" at 11850.76,4434.8 h61.93
  text "GND" at 12225.46,4428.9 h61.93
  text "BOOT0" at 9120.67,4404.83 h60
  text "SWD" at 8723.91,4396.56 h61.93
  text "NSS" at 11871.52,4335.19 h61.93
  text "PB11" at 12230.68,4330.47 h61.93
  text "SWO" at 9124.61,4298.84 h61.93
  text "SWC" at 8720.95,4293.48 h61.93
  text "TX" at 9147.1,4197.39 h61.93
  text "NRST" at 8726.32,4195.36 h61.93
  text "GND" at 8729.57,4094.61 h61.93
  text "RX" at 9151.43,4089.04 h61.93
  text "AT-Link" at 8853.71,3980.2 h82.58
  text "3V3" at 12921.46,3924.01 h62
  text "AT-START-F455 V1.0" at 11230.69,3874.31 h120
  text "USART1_TX" at 12700.8,3822.86 h62
  text "POWER" at 11194.49,3781.08 h61.93
  text "ANALOG IN" at 11702.36,3781.07 h61.93
  text "USART1_RX" at 12700.8,3727.96 h62
  text "IOREF" at 10781.5,3653.97 h70.78 r90
  text "RESET" at 10876.33,3653.59 h70.78 r90
  text "3.3V" at 10977.33,3651.13 h70.78 r90
  text "GND" at 11178.33,3649.66 h70.78 r90
  text "GND" at 11277.62,3649.66 h70.78 r90
  text "5V" at 11077.33,3648.2 h70.78 r90
  text "AN0" at 11575.41,3646.71 h70.78 r90
  text "AN1" at 11672.34,3646.71 h70.78 r90
  text "AN3" at 11873.28,3644.74 h70.78 r90
  text "AN5" at 12077.37,3644.74 h70.78 r90
  text "AN2" at 11775.17,3643.55 h70.78 r90
  text "AN4" at 11977.29,3643.55 h70.78 r90
  text "GND" at 12922.96,3627.85 h62
  text "3V3" at 8437.43,3599.5 h61.93 r270
  text "RESET" at 8892.74,3598.53 h82.58
  text "SWD" at 8348.38,3597.53 h61.93 r270
  text "SWC" at 8249.49,3594.38 h61.93 r270
  text "GND" at 8063.35,3592.36 h61.93 r270
  text "NRST" at 8151.38,3591.91 h61.93 r270
  text "F0" at 9717.75,3430.69 h53.08 r45
  text "A2" at 11016.8,3430.92 h53.08 r45
  text "E11" at 12421.2,3431.34 h53.08 r45
  text "E15" at 12625.13,3429.59 h53.08 r45
  text "BOOT0" at 8348.38,3429.49 h61.93 r270
  text "A0" at 10918.4,3429 h53.08 r45
  text "E13" at 12513.82,3428.86 h53.08 r45
  text "F2" at 9822.53,3428.08 h53.08 r45
  text "A4" at 11221.98,3428.26 h53.08 r45
  text "E9" at 12229.37,3428.26 h53.08 r45
  text "SWO" at 8252.64,3426.93 h61.93 r270
  text "E3" at 9317.76,3427.09 h53.08 r45
  text "F4" at 9922.58,3426.55 h53.08 r45
  text "B0" at 11519.56,3426.9 h53.08 r45
  text "F6" at 10118.12,3425.55 h53.08 r45
  text "H1*" at 10420.77,3425.87 h53.08 r45
  text "E5" at 9426.43,3424.75 h53.08 r45
  text "H4" at 10718.04,3425.31 h53.08 r45
  text "B2" at 11620.73,3425.34 h53.08 r45
  text "F12" at 11719.48,3425.46 h53.08 r45
  text "F14" at 11920.05,3424.78 h53.08 r45
  text "B11" at 12722.85,3425.28 h53.08 r45
  text "F10" at 10317.32,3423.73 h53.08 r45
  text "A6" at 11315.47,3424.27 h53.08 r45
  text "E7" at 12126.2,3424.38 h53.08 r45
  text "F8" at 10221.06,3423.09 h53.08 r45
  text "C2" at 10617.79,3423.01 h53.08 r45
  text "G0" at 12024.4,3422.35 h53.08 r45
  text "C0" at 10516.48,3420.09 h53.08 r45
  text "C4" at 11415.99,3420.01 h53.08 r45
  text "VDD" at 12308.18,3419.91 h53.08 r45
  text "C14*" at 9609.03,3418.94 h53.08 r45
  text "VREF+" at 10776.53,3417.68 h44.24 r30
  text "VDD" at 11807.47,3417.75 h53.08 r45
  text "VDD" at 12810.73,3418.26 h53.08 r45
  text "VBAT" at 9504.82,3417.02 h53.08 r45
  text "GND" at 11114.96,3417.09 h53.08 r45
  text "GND" at 9999.65,3416.16 h53.08 r30
  text "TX" at 8155.32,3409.69 h61.93 r270
  text "5V" at 8436.64,3406.14 h61.93 r270
  text "RX" at 8062.34,3405.35 h61.93 r270
  text "GND" at 13073.57,3305.61 h61.93
  text "USER" at 8908.71,3214.28 h82.58
  text "C1" at 10637.03,3136.76 h53.08 r45
  text "B1" at 11635.5,3133.71 h53.08 r45
  text "G1" at 12137.35,3134.24 h53.08 r45
  text "F5" at 10038.42,3132.15 h53.08 r45
  text "C3" at 10736.94,3132.35 h53.08 r45
  text "F1" at 9841.47,3131.1 h53.08 r45
  text "A5" at 11338.4,3130.12 h53.08 r45
  text "F3" at 9936.58,3128.84 h53.08 r45
  text "E2" at 9335.59,3128.23 h53.08 r45
  text "F9" at 10341.35,3128.11 h53.08 r45
  text "A3" at 11133.89,3128.19 h53.08 r45
  text "C5" at 11536.52,3128.27 h53.08 r45
  text "F11" at 11734.83,3127.56 h53.08 r45
  text "E8" at 12230.09,3128.26 h53.08 r45
  text "A1" at 11037.09,3127.48 h53.08 r45
  text "A7" at 11433.35,3126.7 h53.08 r45
  text "E6" at 9537.6,3126.18 h53.08 r45
  text "E4" at 9431.84,3125.38 h53.08 r45
  text "F7" at 10243.95,3124.35 h53.08 r45
  text "H0*" at 10427.81,3122.94 h53.08 r45
  text "E12" at 12534.33,3122.98 h53.08 r45
  text "H3" at 12838.3,3122.46 h53.08 r45
  text "F13" at 11935.66,3120.69 h53.08 r45
  text "F15" at 12034.14,3120.52 h53.08 r45
  text "E10" at 12438.37,3120.36 h53.08 r45
  text "E14" at 12639.85,3120.08 h53.08 r45
  text "B10" at 12732.23,3120.34 h53.08 r45
  text "C13" at 9633.25,3116.92 h53.08 r45
  text "GND" at 11820.04,3114.32 h53.08 r45
  text "VDD" at 10122.81,3111.97 h53.08 r45
  text "GND" at 10820.45,3112.48 h53.08 r45
  text "VDD" at 11222.75,3108.88 h53.08 r45
  text "GND" at 12321.19,3109.27 h53.08 r45
  text "C15*" at 9724.16,3107.16 h53.08 r45
  text "NRST" at 10521.19,3084.69 h53.08 r45
  text "VDDA" at 10908.51,3083.8 h53.08 r45
  text "1" at 9317.99,3057.82 h52.27
  text "11" at 9823.24,3057.36 h53.08
  text "21" at 10313.01,3057.33 h53.08
  text "31" at 10811.82,3057.33 h53.08
  text "41" at 11307.49,3057.3 h53.08
  text "51" at 11803.16,3057.31 h53.08
  text "61" at 12308.67,3057.31 h53.08
  text "71" at 12819.69,3057.36 h53.08
Bottom Silkscreen Layer:
  text "143" at 9380.01,5855.94 h53.08 r45
  text "139" at 9572.01,5854.79 h53.08 r45
  text "135" at 9788.01,5855.36 h53.08 r45
  text "133" at 9892.01,5855.36 h53.08 r45
  text "129" at 10077.34,5854.79 h53.08 r45
  text "125" at 10280.27,5855.36 h53.08 r45
  text "123" at 10380.27,5855.36 h53.08 r45
  text "109" at 11076.34,5854.79 h53.08 r45
  text "105" at 11285.09,5855.36 h53.08 r45
  text "103" at 11377.86,5855.36 h53.08 r45
  text "141" at 9470.68,5853.05 h53.08 r45
  text "137" at 9681.34,5851.89 h53.08 r45
  text "131" at 9985.34,5852.47 h53.08 r45
  text "127" at 10174.68,5851.89 h53.08 r45
  text "121" at 10477.6,5852.47 h53.08 r45
  text "107" at 11178.09,5851.89 h53.08 r45
  text "101" at 11462.19,5852.47 h53.08 r45
  text "119" at 10573.6,5849.58 h53.08 r45
  text "115" at 10774.94,5850.16 h53.08 r45
  text "113" at 10879.34,5850.16 h53.08 r45
  text "95" at 11766.34,5848.85 h53.08 r45
  text "93" at 11868.48,5848.85 h53.08 r45
  text "85" at 12261.98,5848.85 h53.08 r45
  text "83" at 12369.39,5848.85 h53.08 r45
  text "99" at 11564.48,5848.28 h53.08 r45
  text "89" at 12065.53,5848.28 h53.08 r45
  text "117" at 10674.94,5846.69 h53.08 r45
  text "111" at 10967.34,5847.26 h53.08 r45
  text "79" at 12565.52,5846.54 h53.08 r45
  text "75" at 12767.44,5847.12 h53.08 r45
  text "73" at 12867.15,5847.12 h53.08 r45
  text "91" at 11959.39,5845.96 h53.08 r45
  text "81" at 12466.24,5845.96 h53.08 r45
  text "97" at 11660.48,5845.38 h53.08 r45
  text "87" at 12163.91,5845.38 h53.08 r45
  text "77" at 12665.72,5843.65 h53.08 r45
  text "142" at 9474.68,5579.59 h53.08 r45
  text "132" at 9978.68,5579.01 h53.08 r45
  text "122" at 10468.27,5579.01 h53.08 r45
  text "102" at 11480.29,5579.01 h53.08 r45
  text "144" at 9369.93,5577.28 h53.08 r45
  text "140" at 9576.01,5577.28 h53.08 r45
  text "138" at 9677.34,5577.28 h53.08 r45
  text "134" at 9881.34,5576.7 h53.08 r45
  text "130" at 10070.68,5576.7 h53.08 r45
  text "128" at 10176.01,5577.28 h53.08 r45
  text "124" at 10373.6,5576.7 h53.08 r45
  text "120" at 10580.27,5576.7 h53.08 r45
  text "108" at 11175.34,5577.28 h53.08 r45
  text "104" at 11373.53,5576.7 h53.08 r45
  text "100" at 11574.86,5576.7 h53.08 r45
  text "136" at 9785.34,5576.12 h53.08 r45
  text "126" at 10276.27,5576.12 h53.08 r45
  text "106" at 11265.09,5576.12 h53.08 r45
  text "112" at 10967.01,5573.81 h53.08 r45
  text "118" at 10672.27,5572.07 h53.08 r45
  text "92" at 11965.2,5572.5 h53.08 r45
  text "82" at 12469.15,5572.5 h53.08 r45
  text "116" at 10764.27,5570.91 h53.08 r45
  text "114" at 10867.01,5571.49 h53.08 r45
  text "110" at 11067.34,5571.49 h53.08 r45
  text "98" at 11671.3,5570.77 h53.08 r45
  text "88" at 12172.96,5570.77 h53.08 r45
  text "96" at 11769.96,5569.61 h53.08 r45
  text "94" at 11868.63,5570.19 h53.08 r45
  text "90" at 12071.53,5570.19 h53.08 r45
  text "86" at 12266.87,5569.61 h53.08 r45
  text "84" at 12368.53,5570.19 h53.08 r45
  text "80" at 12571.11,5570.19 h53.08 r45
  text "78" at 12671.73,5569.03 h53.08 r45
  text "76" at 12773.3,5567.87 h53.08 r45
  text "74" at 12873.87,5568.45 h53.08 r45
  text "VDD" at 8473.57,4642.61 h53.08 r270
  text "GND" at 8485.57,3808.61 h53.08
  text "AT32F455ZET7" at 11707.59,3757.38 h232.22
  text "42" at 11372.69,3453.66 h53.08 r45
  text "48" at 11673.41,3451.92 h53.08 r45
  text "40" at 11274.46,3451.34 h53.08 r45
  text "44" at 11469.84,3451.35 h53.08 r45
  text "46" at 11573.41,3450.77 h53.08 r45
  text "22" at 10368.8,3449.61 h53.08 r45
  text "62" at 12371.46,3449.03 h53.08 r45
  text "28" at 10669.28,3447.87 h53.08 r45
  text "32" at 10868.2,3448.45 h53.08 r45
  text "52" at 11870.12,3448.45 h53.08 r45
  text "20" at 10266.44,3447.3 h53.08 r45
  text "24" at 10469.59,3447.29 h53.08 r45
  text "26" at 10566.42,3446.72 h53.08 r45
  text "38" at 11173.03,3446.72 h53.08 r45
  text "58" at 12171.46,3446.72 h53.08 r45
  text "60" at 12270.46,3446.72 h53.08 r45
  text "64" at 12467.79,3446.72 h53.08 r45
  text "68" at 12666.79,3447.29 h53.08 r45
  text "72" at 12867.79,3447.3 h53.08 r45
  text "30" at 10770.34,3446.14 h53.08 r45
  text "34" at 10971.05,3446.14 h53.08 r45
  text "36" at 11070.17,3445.56 h53.08 r45
  text "50" at 11769.69,3446.14 h53.08 r45
  text "54" at 11973.12,3446.14 h53.08 r45
  text "56" at 12071.12,3445.56 h53.08 r45
  text "66" at 12566.79,3446.14 h53.08 r45
  text "70" at 12767.79,3444.98 h53.08 r45
  text "12" at 9860.93,3444.4 h53.08 r45
  text "18" at 10163.68,3442.67 h53.08 r45
  text "10" at 9760.53,3442.09 h53.08 r45
  text "14" at 9960.14,3442.09 h53.08 r45
  text "16" at 10058.56,3441.51 h53.08 r45
  text "4" at 9454.18,3439.81 h52.27 r45
  text "2" at 9353,3438.65 h52.27 r45
  text "6" at 9553.39,3435.76 h52.27 r45
  text "8" at 9655.36,3436.34 h52.27 r45
  text "43" at 11471.07,3178.79 h53.08 r45
  text "45" at 11568.21,3178.79 h53.08 r45
  text "49" at 11771.64,3178.21 h53.08 r45
  text "41" at 11365.35,3175.9 h53.08 r45
  text "23" at 10469.93,3174.74 h53.08 r45
  text "25" at 10569.08,3174.74 h53.08 r45
  text "47" at 11671.07,3175.32 h53.08 r45
  text "29" at 10766.57,3174.16 h53.08 r45
  text "33" at 10967.29,3173.58 h53.08 r45
  text "35" at 11069.12,3173.58 h53.08 r45
  text "53" at 11971.78,3173.58 h53.08 r45
  text "55" at 12067.78,3173.58 h53.08 r45
  text "63" at 12469.45,3174.16 h53.08 r45
  text "65" at 12576.45,3174.16 h53.08 r45
  text "69" at 12769.45,3173.58 h53.08 r45
  text "39" at 11272.12,3173 h53.08 r45
  text "59" at 12269.12,3173 h53.08 r45
  text "21" at 10363.71,3171.85 h53.08 r45
  text "27" at 10672.65,3171.27 h53.08 r45
  text "31" at 10863.71,3170.69 h53.08 r45
  text "51" at 11861.78,3170.69 h53.08 r45
  text "61" at 12366.12,3171.27 h53.08 r45
  text "67" at 12672.45,3170.69 h53.08 r45
  text "13" at 9961.34,3169.53 h53.08 r45
  text "15" at 10068.69,3169.53 h53.08 r45
  text "37" at 11167.83,3170.11 h53.08 r45
  text "57" at 12168.12,3170.11 h53.08 r45
  text "71" at 12864.45,3169.53 h53.08 r45
  text "19" at 10261.81,3168.96 h53.08 r45
  text "11" at 9858.98,3166.64 h53.08 r45
  text "17" at 10164.84,3166.06 h53.08 r45
  text "3" at 9457.35,3162.63 h52.27 r45
  text "5" at 9554.6,3162.63 h52.27 r45
  text "9" at 9752.63,3163.2 h52.27 r45
  text "1" at 9347.12,3160.89 h52.27 r45
  text "7" at 9655.39,3158 h52.27 r45
Mechanical Layer:
  circle w1: c12139.81,4865.97 r62.99
  circle w1: c10139.81,5465.96 r62.99
  circle w1: c10089.81,3565.97 r62.99
  circle w1: c8818.39,5874.63 r62.99
  circle w1: c8818.39,3158.09 r62.99
  circle w1: c13109.73,3158.09 r62.99
  circle w1: c13109.73,5874.63 r62.99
